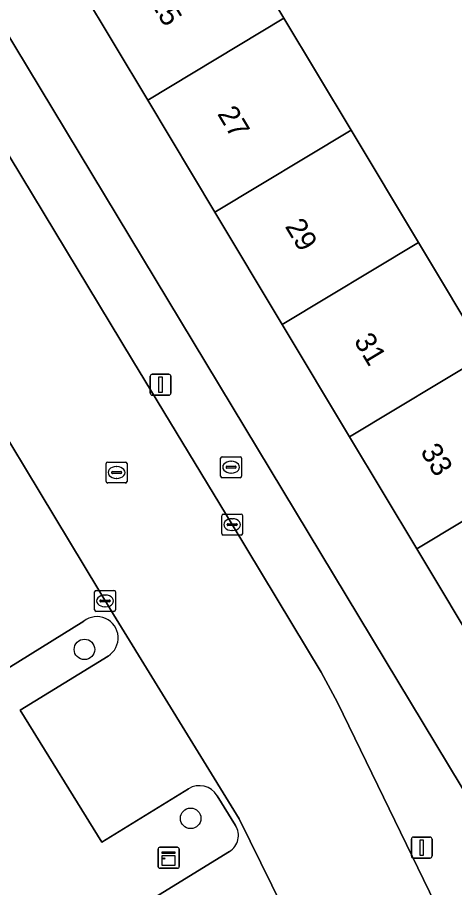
# Model space of a CAD drawing. Extents: x 159888 to 160761, y 384031 to 384750.
# Drawn here: x 160343.33 to 160364.19, y 384559.06 to 384600.57 of the extents above; entities that cross this region are included whole.
import ezdxf

# ---------------------------------------------------------------- set-up
doc = ezdxf.new("R2010")
doc.units = 0
for name, color, linetype in [('IMGEO_Boom', 7, 'Continuous'), ('IMGEO_Brandkraan', 7, 'Continuous'), ('IMGEO_Erf', 7, 'Continuous'), ('IMGEO_Kast', 7, 'Continuous'), ('IMGEO_Kolk', 7, 'Continuous'), ('IMGEO_Lichtmast', 7, 'Continuous'), ('IMGEO_Pand', 7, 'Continuous'), ('IMGEO_Pand_nummerreeks', 7, 'Continuous'), ('IMGEO_Parkeervlak_open', 7, 'Continuous'), ('IMGEO_Rijbaan_lokaal_open', 7, 'Continuous'), ('IMGEO_Rioolput', 7, 'Continuous'), ('IMGEO_Voetpad_open', 7, 'Continuous')]:
    doc.layers.add(name, color=color, linetype=linetype)

msp = doc.modelspace()

# ---------------------------------------------------------------- linework, layer by layer
at = {"layer": 'IMGEO_Boom'}
for centre in [(160346.525, 384570.42), (160351.593, 384562.36)]:
    msp.add_circle(centre, 0.489, dxfattribs=at)
at = {"layer": 'IMGEO_Brandkraan'}
for p, q in [((160353.024, 384578.686), (160353.024, 384579.538)), ((160353.099, 384579.612), (160353.951, 384579.612)), ((160353.512, 384579.392), (160353.537, 384579.392)), ((160354.025, 384579.538), (160354.025, 384578.686)), ((160353.283, 384579.106), (160353.283, 384579.118)), ((160353.721, 384579.069), (160353.323, 384579.069)), ((160353.326, 384579.155), (160353.724, 384579.155)), ((160353.767, 384579.118), (160353.767, 384579.106)), ((160353.951, 384578.612), (160353.099, 384578.612)), ((160353.535, 384578.832), (160353.51, 384578.832))]:
    msp.add_line(p, q, dxfattribs=at)
for points in [[(160353.024, 384578.686), (160353.024, 384579.538)], [(160353.099, 384579.612), (160353.951, 384579.612)], [(160354.025, 384579.538), (160354.025, 384578.686)], [(160353.951, 384578.612), (160353.099, 384578.612)]]:
    msp.add_lwpolyline(points, dxfattribs=at)
for centre, radius, start, end in [((160353.101, 384579.536), 0.0765, 91.552, 178.448), ((160353.101, 384579.536), 0.0765, 91.552, 178.448), ((160353.949, 384579.536), 0.0765, 1.552, 88.448), ((160353.949, 384579.536), 0.0765, 1.552, 88.448), ((160353.323, 384579.115), 0.0403, 85.8775, 175.7526), ((160353.32, 384579.105), 0.0366, 178.938, 274.7102), ((160353.724, 384579.112), 0.043, 264.8664, 352.4533), ((160353.728, 384579.117), 0.0386, 1.7309, 96.639), ((160353.101, 384578.688), 0.0765, 181.552, 268.448), ((160353.101, 384578.688), 0.0765, 181.552, 268.448), ((160353.949, 384578.688), 0.0765, 271.552, 358.448), ((160353.949, 384578.688), 0.0765, 271.552, 358.448)]:
    msp.add_arc(centre, radius, start, end, dxfattribs=at)
for centre, major_axis, ratio, start_param, end_param in [((160353.511, 384579.112), (-0.387, 0.002), 0.722429, 4.712389, 7.853982), ((160353.536, 384579.112), (-0.39, 0.002), 0.717154, 1.570796, 4.712389)]:
    msp.add_ellipse(centre, major_axis=major_axis, ratio=ratio, start_param=start_param, end_param=end_param, dxfattribs=at)
at = {"layer": 'IMGEO_Erf'}
for points in [[(160365.594, 384569.857), (160362.384, 384575.21), (160359.174, 384580.564), (160355.965, 384585.916), (160352.755, 384591.269), (160349.544, 384596.624), (160346.334, 384601.977), (160344.717, 384604.674), (160344.098, 384604.301), (160342.498, 384606.954), (160340.947, 384609.527), (160341.551, 384609.892), (160339.88, 384612.664), (160336.657, 384618.009), (160333.34, 384623.511), (160333.197, 384623.748), (160332.498, 384623.327), (160331.061, 384625.711), (160331.76, 384626.133), (160330.122, 384628.85), (160326.591, 384626.72), (160327.382, 384625.41), (160378.5, 384540.702)], [(160352.838, 384605.889), (160356.047, 384600.536), (160359.258, 384595.182), (160362.468, 384589.829), (160365.677, 384584.476)]]:
    msp.add_lwpolyline(points, dxfattribs=at)
at = {"layer": 'IMGEO_Kast'}
for p, q in [((160350.043, 384560.056), (160350.043, 384560.897)), ((160350.043, 384560.897), (160350.043, 384560.056)), ((160350.118, 384560.981), (160350.959, 384560.981)), ((160350.959, 384560.981), (160350.118, 384560.981)), ((160351.043, 384560.906), (160351.043, 384560.065)), ((160351.043, 384560.065), (160351.043, 384560.906)), ((160350.968, 384559.981), (160350.127, 384559.981)), ((160350.127, 384559.981), (160350.968, 384559.981))]:
    msp.add_line(p, q, dxfattribs=at)
for points in [[(160350.238, 384560.771), (160350.838, 384560.771), (160350.838, 384560.686), (160350.238, 384560.686), (160350.238, 384560.771)], [(160350.238, 384560.596), (160350.838, 384560.596), (160350.838, 384560.107), (160350.238, 384560.107), (160350.238, 384560.596)]]:
    msp.add_lwpolyline(points, dxfattribs=at)
msp.add_circle((160350.322, 384560.445), 0.0377, dxfattribs=at)
for centre, start, end in [((160350.121, 384560.903), 92.4484, 184.2845), ((160350.121, 384560.903), 92.4484, 184.2845), ((160350.965, 384560.903), 2.4484, 94.2845), ((160350.965, 384560.903), 2.4484, 94.2845), ((160350.121, 384560.059), 182.4484, 274.2845), ((160350.121, 384560.059), 182.4484, 274.2845), ((160350.965, 384560.059), 272.4484, 4.2845), ((160350.965, 384560.059), 272.4484, 4.2845)]:
    msp.add_arc(centre, 0.0779, start, end, dxfattribs=at)
at = {"layer": 'IMGEO_Kolk'}
for p, q in [((160353.15, 384576.872), (160354.002, 384576.872)), ((160353.075, 384575.946), (160353.075, 384576.798)), ((160353.377, 384576.415), (160353.775, 384576.415)), ((160353.563, 384576.652), (160353.588, 384576.652)), ((160354.076, 384576.798), (160354.076, 384575.946)), ((160353.334, 384576.366), (160353.334, 384576.378)), ((160353.772, 384576.329), (160353.374, 384576.329)), ((160353.586, 384576.092), (160353.561, 384576.092)), ((160353.818, 384576.378), (160353.818, 384576.366)), ((160354.002, 384575.872), (160353.15, 384575.872)), ((160347.009, 384572.307), (160347.009, 384573.159)), ((160347.084, 384573.233), (160347.936, 384573.233)), ((160348.01, 384573.159), (160348.01, 384572.307)), ((160347.268, 384572.727), (160347.268, 384572.739)), ((160347.706, 384572.69), (160347.308, 384572.69)), ((160347.311, 384572.776), (160347.709, 384572.776)), ((160347.497, 384573.013), (160347.522, 384573.013)), ((160347.752, 384572.739), (160347.752, 384572.727)), ((160347.52, 384572.453), (160347.495, 384572.453)), ((160347.936, 384572.233), (160347.084, 384572.233))]:
    msp.add_line(p, q, dxfattribs=at)
for points in [[(160353.15, 384576.872), (160354.002, 384576.872)], [(160353.075, 384575.946), (160353.075, 384576.798)], [(160354.076, 384576.798), (160354.076, 384575.946)], [(160354.002, 384575.872), (160353.15, 384575.872)], [(160347.009, 384572.307), (160347.009, 384573.159)], [(160347.084, 384573.233), (160347.936, 384573.233)], [(160348.01, 384573.159), (160348.01, 384572.307)], [(160347.936, 384572.233), (160347.084, 384572.233)]]:
    msp.add_lwpolyline(points, dxfattribs=at)
for centre, radius, start, end in [((160353.152, 384576.796), 0.0765, 91.552, 178.448), ((160353.152, 384576.796), 0.0765, 91.552, 178.448), ((160354, 384576.796), 0.0765, 1.552, 88.448), ((160354, 384576.796), 0.0765, 1.552, 88.448), ((160353.374, 384576.375), 0.0403, 85.8775, 175.7526), ((160353.779, 384576.377), 0.0386, 1.7309, 96.639), ((160353.371, 384576.365), 0.0366, 178.938, 274.7102), ((160353.775, 384576.372), 0.043, 264.8664, 352.4533), ((160353.152, 384575.948), 0.0765, 181.552, 268.448), ((160353.152, 384575.948), 0.0765, 181.552, 268.448), ((160354, 384575.948), 0.0765, 271.552, 358.448), ((160354, 384575.948), 0.0765, 271.552, 358.448), ((160347.086, 384573.157), 0.0765, 91.552, 178.448), ((160347.086, 384573.157), 0.0765, 91.552, 178.448), ((160347.934, 384573.157), 0.0765, 1.552, 88.448), ((160347.934, 384573.157), 0.0765, 1.552, 88.448), ((160347.308, 384572.736), 0.0403, 85.8775, 175.7526), ((160347.305, 384572.726), 0.0366, 178.938, 274.7102), ((160347.709, 384572.733), 0.043, 264.8664, 352.4533), ((160347.713, 384572.738), 0.0386, 1.7309, 96.639), ((160347.086, 384572.309), 0.0765, 181.552, 268.448), ((160347.086, 384572.309), 0.0765, 181.552, 268.448), ((160347.934, 384572.309), 0.0765, 271.552, 358.448), ((160347.934, 384572.309), 0.0765, 271.552, 358.448)]:
    msp.add_arc(centre, radius, start, end, dxfattribs=at)
for centre, major_axis, ratio, start_param, end_param in [((160353.562, 384576.372), (-0.387, 0.002), 0.722429, 4.712389, 7.853982), ((160353.587, 384576.372), (-0.39, 0.002), 0.717154, 1.570796, 4.712389), ((160347.496, 384572.733), (-0.387, 0.002), 0.722429, 4.712389, 7.853982), ((160347.521, 384572.733), (-0.39, 0.002), 0.717154, 1.570796, 4.712389)]:
    msp.add_ellipse(centre, major_axis=major_axis, ratio=ratio, start_param=start_param, end_param=end_param, dxfattribs=at)
at = {"layer": 'IMGEO_Lichtmast'}
for p, q in [((160349.763, 384583.546), (160350.553, 384583.546)), ((160350.553, 384583.546), (160349.763, 384583.546)), ((160349.663, 384582.646), (160349.663, 384583.446)), ((160349.663, 384583.446), (160349.663, 384582.646)), ((160350.653, 384583.446), (160350.653, 384582.646)), ((160350.653, 384582.646), (160350.653, 384583.446)), ((160350.553, 384582.546), (160349.763, 384582.546)), ((160349.763, 384582.546), (160350.553, 384582.546)), ((160362.227, 384561.466), (160363.017, 384561.466)), ((160363.017, 384561.466), (160362.227, 384561.466)), ((160362.127, 384560.566), (160362.127, 384561.366)), ((160362.127, 384561.366), (160362.127, 384560.566)), ((160363.117, 384561.366), (160363.117, 384560.566)), ((160363.117, 384560.566), (160363.117, 384561.366)), ((160363.017, 384560.466), (160362.227, 384560.466)), ((160362.227, 384560.466), (160363.017, 384560.466))]:
    msp.add_line(p, q, dxfattribs=at)
for points in [[(160350.083, 384583.421), (160350.233, 384583.421), (160350.233, 384582.671), (160350.083, 384582.671), (160350.083, 384583.421)], [(160362.547, 384561.341), (160362.697, 384561.341), (160362.697, 384560.591), (160362.547, 384560.591), (160362.547, 384561.341)]]:
    msp.add_lwpolyline(points, dxfattribs=at)
for centre, start, end in [((160349.763, 384583.446), 90, 180), ((160349.763, 384583.446), 90, 180), ((160350.553, 384583.446), 0, 90), ((160350.553, 384583.446), 360, 90), ((160349.763, 384582.646), 180, 270), ((160349.763, 384582.646), 180, 270), ((160350.553, 384582.646), 270, 0), ((160350.553, 384582.646), 270, 0), ((160362.227, 384561.366), 90, 180), ((160362.227, 384561.366), 90, 180), ((160363.017, 384561.366), 0, 90), ((160363.017, 384561.366), 360, 90), ((160362.227, 384560.566), 180, 270), ((160362.227, 384560.566), 180, 270), ((160363.017, 384560.566), 270, 0), ((160363.017, 384560.566), 270, 0)]:
    msp.add_arc(centre, 0.1, start, end, dxfattribs=at)
at = {"layer": 'IMGEO_Pand'}
for points in [[(160346.334, 384601.977), (160349.544, 384596.624), (160356.047, 384600.536), (160352.838, 384605.889)], [(160356.047, 384600.536), (160349.544, 384596.624), (160352.755, 384591.269), (160359.258, 384595.182)], [(160359.258, 384595.182), (160352.755, 384591.269), (160355.965, 384585.916), (160362.468, 384589.829)], [(160362.468, 384589.829), (160355.965, 384585.916), (160359.174, 384580.564), (160365.677, 384584.476)], [(160359.174, 384580.564), (160362.384, 384575.21), (160368.888, 384579.122), (160365.677, 384584.476)], [(160372.097, 384573.77), (160368.888, 384579.122), (160362.384, 384575.21), (160365.594, 384569.857)]]:
    msp.add_lwpolyline(points, close=True, dxfattribs=at)
at = {"layer": 'IMGEO_Parkeervlak_open'}
for points in [[(160357.029, 384556.009), (160353.913, 384562.344), (160347.907, 384572.079), (160338.841, 384587.096), (160333.917, 384595.23)], [(160342.733, 384578.14), (160338.577, 384575.576), (160342.404, 384569.244), (160346.493, 384571.766)], [(160347.658, 384570.104), (160343.464, 384567.516), (160347.35, 384561.217), (160351.485, 384563.768)], [(160352.862, 384563.442), (160353.738, 384562.022)], [(160353.445, 384560.784), (160349.225, 384558.18), (160351.833, 384553.951), (160355.732, 384556.356)]]:
    msp.add_lwpolyline(points, dxfattribs=at)
for centre, radius, start, end in [((160347.121, 384570.967), 1.016, 301.9139, 128.1442), ((160352.01, 384562.916), 1.001, 31.7062, 121.6551), ((160352.973, 384561.549), 0.899, 301.6582, 31.7112)]:
    msp.add_arc(centre, radius, start, end, dxfattribs=at)
at = {"layer": 'IMGEO_Rijbaan_lokaal_open'}
msp.add_lwpolyline([(160365.031, 384554.673), (160363.537, 384557.75), (160358.601, 384567.882), (160357.819, 384569.337), (160353.575, 384576.372), (160348.814, 384584.217), (160340.324, 384598.252), (160339.964, 384598.8), (160333.917, 384595.23), (160338.841, 384587.096), (160347.907, 384572.079), (160353.913, 384562.344), (160357.029, 384556.009), (160357.37, 384555.288), (160358.288, 384553.023), (160359.37, 384549.992), (160360.299, 384546.003), (160360.9, 384542.73), (160361.069, 384541.808), (160361.78, 384537.571), (160363.175, 384514.863), (160363.478, 384506.755), (160363.686, 384500)], dxfattribs=at)
at = {"layer": 'IMGEO_Rioolput'}
for p, q in [((160347.636, 384579.358), (160348.488, 384579.358)), ((160347.561, 384578.432), (160347.561, 384579.284)), ((160347.863, 384578.901), (160348.261, 384578.901)), ((160348.049, 384579.138), (160348.074, 384579.138)), ((160348.562, 384579.284), (160348.562, 384578.432)), ((160347.82, 384578.852), (160347.82, 384578.864)), ((160348.258, 384578.815), (160347.86, 384578.815)), ((160348.072, 384578.578), (160348.047, 384578.578)), ((160348.304, 384578.864), (160348.304, 384578.852)), ((160348.488, 384578.358), (160347.636, 384578.358))]:
    msp.add_line(p, q, dxfattribs=at)
for points in [[(160347.636, 384579.358), (160348.488, 384579.358)], [(160347.561, 384578.432), (160347.561, 384579.284)], [(160348.562, 384579.284), (160348.562, 384578.432)], [(160348.488, 384578.358), (160347.636, 384578.358)]]:
    msp.add_lwpolyline(points, dxfattribs=at)
for centre, radius, start, end in [((160347.638, 384579.282), 0.0765, 91.552, 178.448), ((160347.638, 384579.282), 0.0765, 91.552, 178.448), ((160348.486, 384579.282), 0.0765, 1.552, 88.448), ((160348.486, 384579.282), 0.0765, 1.552, 88.448), ((160347.86, 384578.861), 0.0403, 85.8775, 175.7526), ((160348.265, 384578.863), 0.0386, 1.7309, 96.639), ((160347.857, 384578.851), 0.0366, 178.938, 274.7102), ((160348.261, 384578.858), 0.043, 264.8664, 352.4533), ((160347.638, 384578.434), 0.0765, 181.552, 268.448), ((160347.638, 384578.434), 0.0765, 181.552, 268.448), ((160348.486, 384578.434), 0.0765, 271.552, 358.448), ((160348.486, 384578.434), 0.0765, 271.552, 358.448)]:
    msp.add_arc(centre, radius, start, end, dxfattribs=at)
for centre, major_axis, ratio, start_param, end_param in [((160348.048, 384578.858), (-0.387, 0.002), 0.722429, 4.712389, 7.853982), ((160348.073, 384578.858), (-0.39, 0.002), 0.717154, 1.570796, 4.712389)]:
    msp.add_ellipse(centre, major_axis=major_axis, ratio=ratio, start_param=start_param, end_param=end_param, dxfattribs=at)
at = {"layer": 'IMGEO_Voetpad_open'}
for points in [[(160298.109, 384667.759), (160306.181, 384654.411), (160307.199, 384652.736), (160310.692, 384646.906), (160320.969, 384630.093), (160324.715, 384623.983), (160324.799, 384623.845), (160328.781, 384617.284), (160328.88, 384617.141), (160339.964, 384598.8), (160340.324, 384598.252), (160348.814, 384584.217), (160353.575, 384576.372), (160357.819, 384569.337), (160358.601, 384567.882), (160363.537, 384557.75), (160365.031, 384554.673)], [(160378.5, 384540.702), (160327.382, 384625.41), (160326.591, 384626.72), (160325.907, 384627.855), (160326.852, 384628.447), (160325.759, 384630.237), (160321.118, 384637.836), (160319.784, 384640.021), (160314.471, 384648.719), (160313.133, 384650.91), (160312.719, 384651.588), (160309.591, 384656.709), (160306.013, 384662.568), (160304.678, 384664.753), (160304.243, 384665.466)], [(160346.493, 384571.766), (160342.404, 384569.244), (160338.577, 384575.576)], [(160351.485, 384563.768), (160347.35, 384561.217), (160343.464, 384567.516), (160347.658, 384570.104)], [(160353.738, 384562.022), (160352.862, 384563.442)], [(160355.732, 384556.356), (160351.833, 384553.951), (160349.225, 384558.18), (160353.445, 384560.784)]]:
    msp.add_lwpolyline(points, dxfattribs=at)
for centre, radius, start, end in [((160347.121, 384570.967), 1.016, 301.9139, 128.1442), ((160352.01, 384562.916), 1.001, 31.7062, 121.6551), ((160352.973, 384561.549), 0.899, 301.6582, 31.7112)]:
    msp.add_arc(centre, radius, start, end, dxfattribs=at)

# ---------------------------------------------------------------- texts
at = {"layer": 'IMGEO_Pand_nummerreeks'}
for s, p in [('25', (160349.615, 384601.336)), ('27', (160352.844, 384595.969)), ('29', (160356.073, 384590.601)), ('31', (160359.36, 384585.138)), ('33', (160362.531, 384579.866))]:
    msp.add_text(s, height=1, rotation=301.0302, dxfattribs=at).set_placement(p)

doc.saveas('drawing.dxf')
